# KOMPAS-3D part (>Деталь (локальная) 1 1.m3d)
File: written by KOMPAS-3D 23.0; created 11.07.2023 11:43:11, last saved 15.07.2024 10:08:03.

Document properties: Автор: Владимир; Полное имя файла: C:\Users\YNA_NN\AppData\Local\Temp\KOMPAS-3D\ktff-db8b-4e68-b191\_Деталь (локальная) 1 1.m3d

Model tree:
1. Эскиз:1
2. Элемент выдавливания:2  (labels: Сталь 3сп ГОСТ 380-2005)
     Расстояние 1 = 100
